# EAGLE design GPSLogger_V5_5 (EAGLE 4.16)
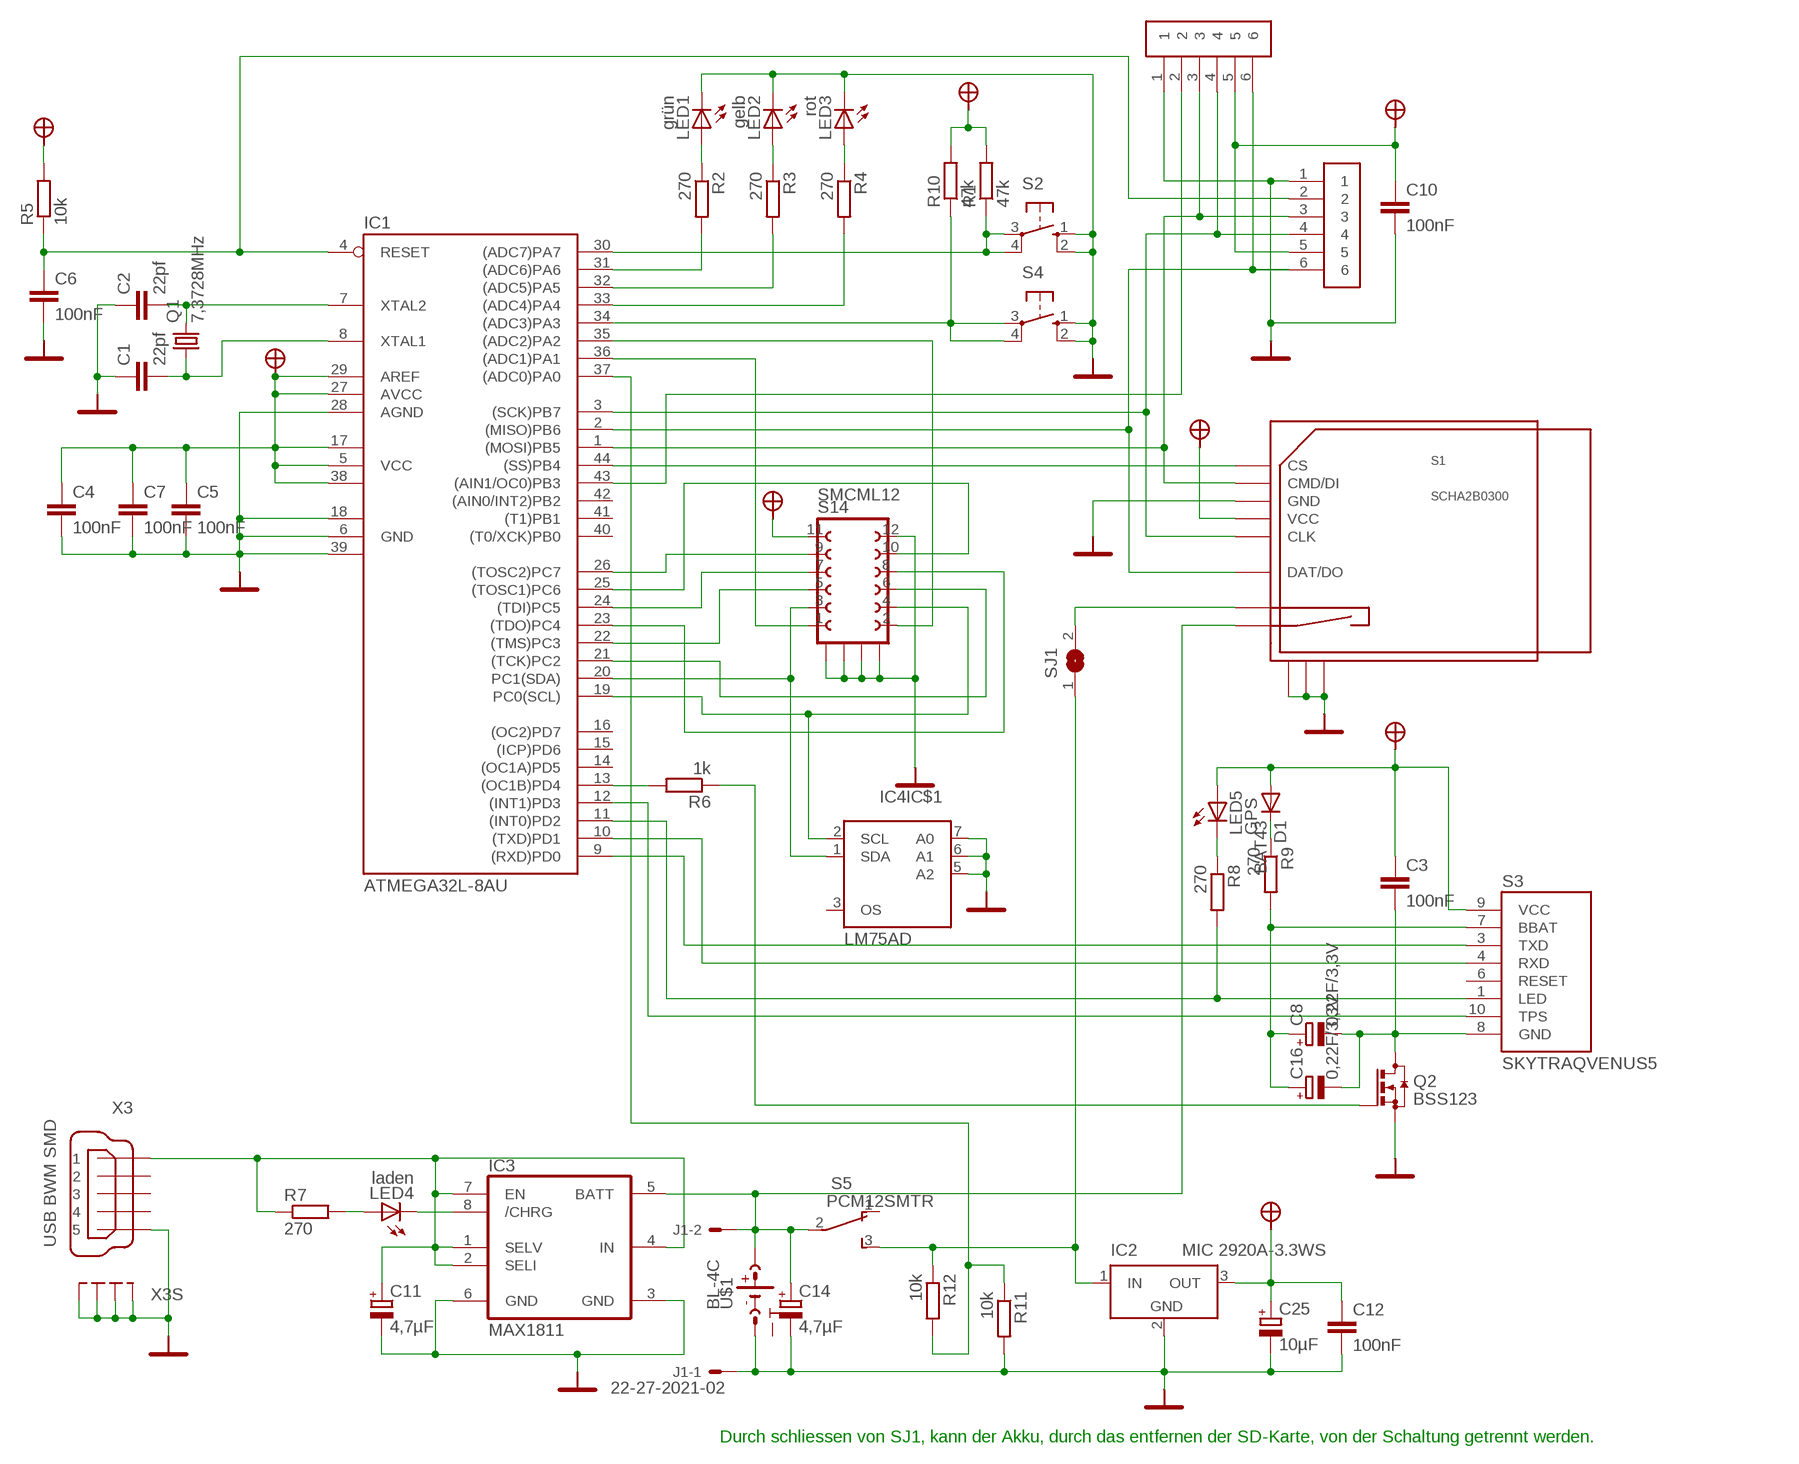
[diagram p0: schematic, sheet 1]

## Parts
C1  22pf  C-EUC0805K  [C0805K]
C2  22pf  C-EUC0805K  [C0805K]
C3  100nF  C-EUC0805K  [C0805K]
C4  100nF  C-EUC0805K  [C0805K]
C5  100nF  C-EUC0805K  [C0805K]
C6  100nF  C-EUC0805K  [C0805K]
C7  100nF  C-EUC0805K  [C0805K]
C8  0,22F/3,3V  EDLEN204XX3R3SA  [EDLEN204A3R3S]
C10  100nF  C-EUC0805K  [C0805K]
C11  4,7µF  CPOL-EUCT3528  [CT3528]
C12  100nF  C-EUC0805K  [C0805K]
C14  4,7µF  CPOL-EUCT3528  [CT3528]
C16  0,22F/3,3V  GOLDCAP  [C]
C25  10µF  CPOL-EUCT3528  [CT3528]
D1  BAT43  DIODE-SOD106A-R  [SOD106A-R]
IC1  ATMEGA32L-8AU  MEGA32-A  [TQFP44]
IC2  MIC 2920A-3.3WS  LT1129CST5  [SOT223]
IC3  MAX1811  [SO08]
IC4  LM75AD  [SO08]
J1  22-27-2021-02  [6410-02]
LED1  grün  LEDCHIPLED_0805  [CHIPLED_0805]
LED2  gelb  LEDCHIPLED_0805  [CHIPLED_0805]
LED3  rot  LEDCHIPLED_0805  [CHIPLED_0805]
LED4  laden  LEDCHIPLED_0805  [CHIPLED_0805]
LED5  GPS  LEDCHIPLED_0805  [CHIPLED_0805]
Q1  7,3728MHz  CRYSTALHC49UP  [HC49UP]
Q2  BSS123  [SOT23]
R1  47k  R-EU_M0805  [M0805]
R2  270  R-EU_M0805  [M0805]
R3  270  R-EU_M0805  [M0805]
R4  270  R-EU_M0805  [M0805]
R5  10k  R-EU_M0805  [M0805]
R6  1k  R-EU_M0805  [M0805]
R7  270  R-EU_M0805  [M0805]
R8  270  R-EU_M0805  [M0805]
R9  270  R-EU_M0805  [M0805]
R10  47k  R-EU_M0805  [M0805]
R11  10k  R-EU_M0805  [M0805]
R12  10k  R-EU_M0805  [M0805]
S1  SCHA2B0300  SD_MICRO  [MICROSD]
S2  10-XX_SMD  [B3F-10XX_SMD]
S3  SKYTRAQVENUS5  [SKYTRAQVENUS5]
S4  10-XX_SMD  [B3F-10XX_SMD]
S5  PCM12SMTR  [PCM12SMTR]
S14  SMCML12  [SMCML12]
SJ1  SJ  [SJ]
U$1  BL-4C  [BL-4C]
U$2  ISP  STECKERSMD6POL  [STECKERSMD6]
U$5  ISP  STECKERSMD6POL  [STECKERSMD6]
X3  USB BWM SMD  MINI-USB_SHIELD5P4-32005-400  [32005-400]

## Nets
3,7V: IC2.1(IN) R12.1 S5.3(S) SJ1.1
5V1: C11.+ IC3.1(SELV) IC3.2(SELI) IC3.4(IN) IC3.7(EN) R7.1 X3.1
BUFFERBATTERIE: C8.+(+1) C16.+(+1) R9.2 S3.7(BBAT)
CS_GPS: IC1.13((OC1B)PD4) R6.2
CS_SD: IC1.44((SS)PB4) S1.2(CS)
GND: C1.1 C2.1 C4.2 C5.2 C6.2 C7.2 C10.2 C11.- C12.2 C14.- C25.- IC1.6(GND) IC1.18(GND1) IC1.28(AGND) IC1.39(GND2) IC2.2(GND) IC3.3(GND) IC3.6(GND) IC4.5(IC$1:A2) IC4.6(IC$1:A1) IC4.7(IC$1:A0) J1.1 LED1.C LED2.C LED3.C Q2.2(S) R11.2 S1.6(GND) S1.GND@1(GND) S1.GND@2(GND) S1.GND@3(GND) S2.1(S) S2.2(S1) S4.1(S) S4.2(S1) S14.12 S14.GND@1 S14.GND@2 S14.GND@3 S14.GND@4 U$1.- U$2.1 U$5.1 X3.5 X3.M1(S1) X3.M2(S2) X3.M3(S3) X3.M4(S4)
GPSTPS: IC1.12((INT1)PD3) S3.10(TPS)
LEDFEHLER: IC1.33((ADC4)PA4) R4.2
LEDGELB: IC1.32((ADC5)PA5) R3.2
LEDGPS: IC1.11((INT0)PD2) R8.2 S3.1(LED)
LEDGRÜN: IC1.31((ADC6)PA6) R2.2
LEDLADEN: IC3.8(/CHRG) LED4.C
MISO: IC1.2((MISO)PB6) S1.7(DAT/DO) U$2.6 U$5.6
MOSI: IC1.1((MOSI)PB5) S1.3(CMD/DI) U$2.3 U$5.3
N$1: IC1.43((AIN1/OC0)PB3) U$5.2
N$2: LED5.C R8.1
N$3: C2.2 IC1.7(XTAL2) Q1.2
N$4: C1.2 IC1.8(XTAL1) Q1.1
N$5: LED1.A R2.1
N$6: LED3.A R4.1
N$12: LED2.A R3.1
N$16: C3.2 C8.-(-1) C16.-(-1) Q2.3(D) S3.8(GND)
N$17: Q2.1(G) R6.1
N$22: S1.S1 SJ1.2
N$23: D1.C R9.1
N$25: LED4.A R7.2
PA0: IC1.37((ADC0)PA0) R11.1 R12.2
PA1: IC1.36((ADC1)PA1) S14.1
PA2: IC1.35((ADC2)PA2) S14.2
PC0: IC1.19(PC0(SCL)) IC4.2(IC$1:SCL) S14.4
PC1: IC1.20(PC1(SDA)) IC4.1(IC$1:SDA) S14.3
PC2: IC1.21((TCK)PC2) S14.6
PC3: IC1.22((TMS)PC3) S14.5
PC4: IC1.23((TDO)PC4) S14.8
PC5: IC1.24((TDI)PC5) S14.7
PC6: IC1.25((TOSC1)PC6) S14.10
PC7: IC1.26((TOSC2)PC7) S14.9
RESET: C6.1 IC1.4(RESET) R5.1 U$2.2
RXD: IC1.9((RXD)PD0) S3.3(TXD)
SCK: IC1.3((SCK)PB7) S1.5(CLK) U$2.4 U$5.4
TASTEROPTIONAL: IC1.34((ADC3)PA3) R10.1 S4.3(P) S4.4(P1)
TASTERSTART: IC1.30((ADC7)PA7) R1.1 S2.3(P) S2.4(P1)
TXD: IC1.10((TXD)PD1) S3.4(RXD)
VBATT: C14.+ IC3.5(BATT) J1.2 S1.S S5.2(P) U$1.+
VCC: C3.1 C4.1 C5.1 C7.1 C10.1 C12.1 C25.+ D1.A IC1.5(VCC) IC1.17(VCC1) IC1.27(AVCC) IC1.29(AREF) IC1.38(VCC2) IC2.3(OUT) LED5.A R1.2 R5.2 R10.2 S1.4(VCC) S3.9(VCC) S14.11 U$2.5 U$5.5
Unconnected: IC1.14((OC1A)PD5) IC1.15((ICP)PD6) IC1.16((OC2)PD7) IC1.40((T0/XCK)PB0) IC1.41((T1)PB1) IC1.42((AIN0/INT2)PB2) IC4.3(IC$1:OS) S3.6(RESET) S5.1(O) U$1.T X3.2 X3.3 X3.4

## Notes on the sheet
- Durch schliessen von SJ1, kann der Akku, durch das entfernen der SD-Karte, von der Schaltung getrennt werden.

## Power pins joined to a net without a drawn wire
GND: IC2.4(GND) IC4.4(PWR:GND) S5.GND@1(GND) S5.GND@2(GND) S5.GND@3(GND) S5.GND@4(GND)
VCC: IC4.8(PWR:VCC)

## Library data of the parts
C1-C7 C10 C12 = rcl:C-EU: CAPACITOR, European symbol
C8 = Sonstige:EDLEN204XX3R3S
C11 C14 C25 = rcl:CPOL-EU: POLARIZED CAPACITOR, European symbol
C16 = Sonstige:GOLDCAP
D1 = diode:DIODE-: DIODE
IC1 = atmel:MEGA32: MICROCONTROLLER 32 Kbytes FLASH 2 Kbytes SRAM 1 Kbytes EEPROM USART 8-channel 10 bit ADC Source: www.atmel.com .. doc2503.pdf
IC2 = linear-technology:LT1129CST5: VOLTAGE REGULATOR with shutdown
IC3 = max1811:MAX1811
IC4 = i2c:LM75AD: Digital Temperature Sensor and Thermal Watchdog
J1 = con-molex:22-?-02: CONNECTOR
LED1-LED5 = led:LED: LED
Q1 = crystal:CRYSTAL: CRYSTAL
Q2 = transistor-small-signal:BSS123: N-CHANNEL MOS FET
R1-R12 = rcl:R-EU_: RESISTOR, European symbol
S1 = MMC:SD_MICRO
S2 S4 = switch-omron:10-XX_SMD
S3 = SkyTraq:SKYTRAQVENUS5
S5 = CKComponents:PCM12SMTR
S14 = Reichelt:SMCML12
SJ1 = jumper:SJ: SMD solder JUMPER
U$1 = Nokia:BL-4C
U$2 U$5 = Sonstige:STECKERSMD6POL
X3 = con-cypressindustries:MINI-USB_SHIELD5P4-: MINI USB-B R/A W/O POST 5 pol. Source: www.cypressindustries.com

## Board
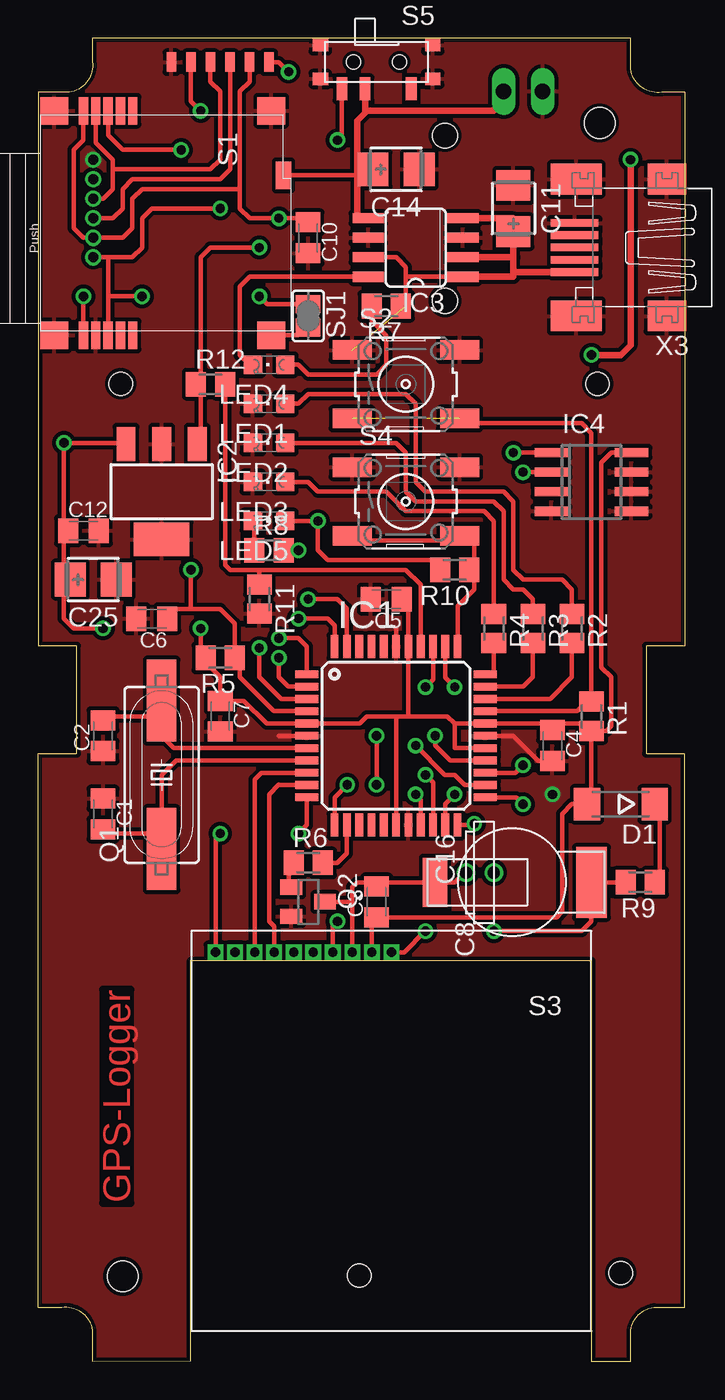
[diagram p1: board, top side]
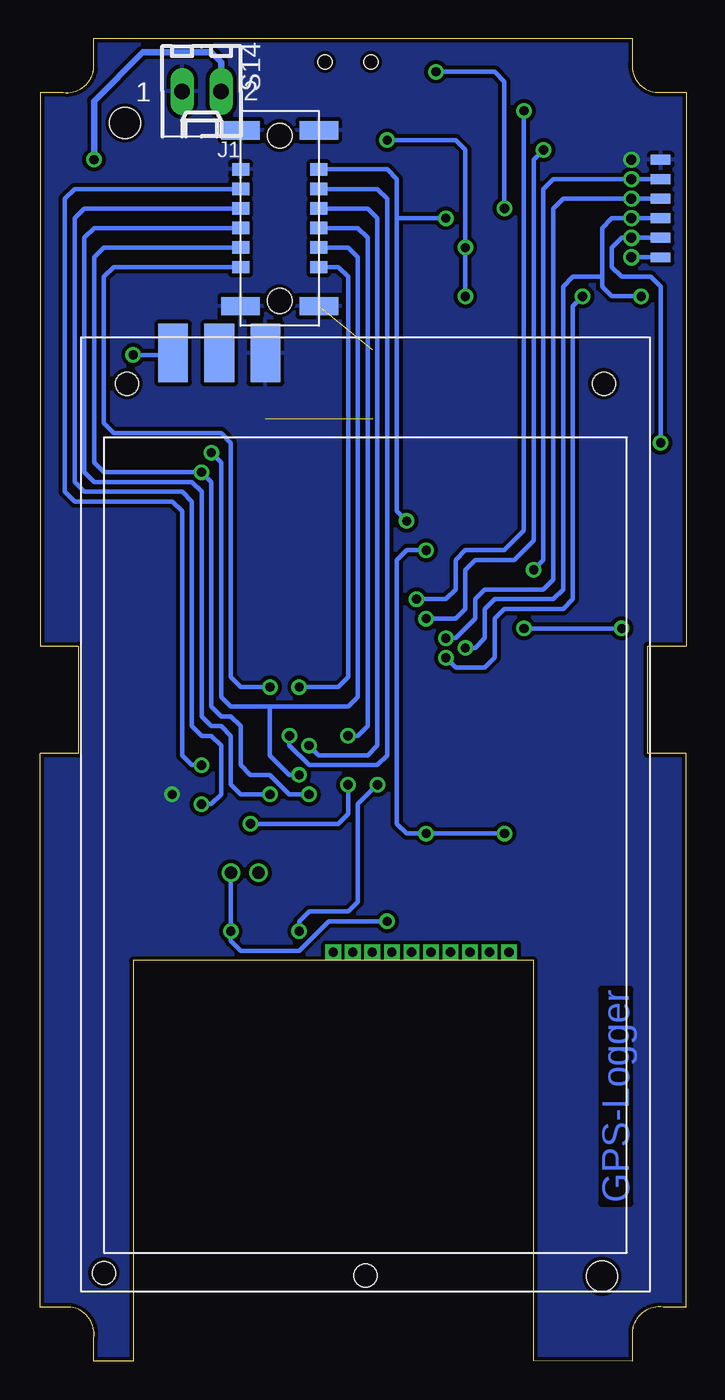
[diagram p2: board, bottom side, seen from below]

Size 42 x 86 mm. Coordinates in mm from the lower left corner, seen from the top.
Outline: 42,3.5 42,39.5 39.5,39.5 39.5,46.5 42,46.5 42,82.5 40.5,82.5 arc-90 38.5,84 38.5,86 3.5,86 3.5,84.5 arc-90 2,82.5 0,82.5 0,46.5 2.5,46.5 2.5,39.5 0,39.5 0,3.5 1.5,3.5 arc-90 3.5,2 3.5,0 9.91,0.01 9.91,26.05 35.95,26.05 35.95,0 38.5,0 38.5,1.5 arc-90 40,3.5 42,3.5
Copper layers (1*16): Top 0.035mm / dielectric 1.5mm / Bottom 0.035mm
Design rules "zwilling": minimum track width 8mil, minimum drill 20mil, track to track 8mil, track to pad 8mil, pad to pad 8mil, via to via 8mil, smd to smd 0mil, copper to edge 10mil, drill to drill 10mil, minimum pad ring 8mil, minimum via ring 8mil, stop-mask expansion 4mil, vias tented up to drill 0mil, thermal gap 10mil
Holes 2 mm at 5.48,5.51 36.48,80.51
Holes 1.5 mm at 37.85,5.73
tKeepout: area 3.5,3.5 to 7.5,7.5; area 34.5,78.5 to 38.5,82.5

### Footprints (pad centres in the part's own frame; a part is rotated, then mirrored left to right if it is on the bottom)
C0805K = smd 1.3 x 1.6: 1 -1,0; 2 1,0
EDLEN204A3R3S = smd 4.6 x 2: + 0,10.16 | smd 3.2 x 1.6: - 0,0
CT3528 = smd 2 x 2.2: + 1.5,0; - -1.5,0
C = drill 0.8 round: + 0,0; - 1.8,0
SOD106A-R = smd 1.7 x 2.1: A 2.2,0; C -2.2,0
TQFP44 = smd 1.5 x 0.5: 1 -5.8,4; 2 -5.8,3.2; 3 -5.8,2.4; 4 -5.8,1.6; 5 -5.8,0.8; 6 -5.8,0; 7 -5.8,-0.8; 8 -5.8,-1.6; 9 -5.8,-2.4; 10 -5.8,-3.2; 11 -5.8,-4; 23 5.8,-4; 24 5.8,-3.2; 25 5.8,-2.4; 26 5.8,-1.6; 27 5.8,-0.8; 28 5.8,0; 29 5.8,0.8; 30 5.8,1.6; 31 5.8,2.4; 32 5.8,3.2; 33 5.8,4 | smd 0.5 x 1.5: 12 -4,-5.8; 13 -3.2,-5.8; 14 -2.4,-5.8; 15 -1.6,-5.8; 16 -0.8,-5.8; 17 0,-5.8; 18 0.8,-5.8; 19 1.6,-5.8; 20 2.4,-5.8; 21 3.2,-5.8; 22 4,-5.8; 34 4,5.8; 35 3.2,5.8; 36 2.4,5.8; 37 1.6,5.8; 38 0.8,5.8; 39 0,5.8; 40 -0.8,5.8; 41 -1.6,5.8; 42 -2.4,5.8; 43 -3.2,5.8; 44 -4,5.8
SOT223 = smd 1.219 x 2.235: 1 -2.311,-3.099; 2 0,-3.099; 3 2.311,-3.099 | smd 3.6 x 2.2: 4 0,3.099
SO08 = smd 0.66 x 2.032: 1 -1.905,-3.073; 2 -0.635,-3.073; 3 0.635,-3.073; 4 1.905,-3.073; 5 1.905,3.073; 6 0.635,3.073; 7 -0.635,3.073; 8 -1.905,3.073
SO08' = smd 0.6 x 2.2: 1 -1.905,-2.6; 2 -0.635,-2.6; 3 0.635,-2.6; 4 1.905,-2.6; 5 1.905,2.6; 6 0.635,2.6; 7 -0.635,2.6; 8 -1.905,2.6
6410-02 = drill 1.016 long: 1 1.27,0; 2 -1.27,0
CHIPLED_0805 = smd 1.2 x 1.2: A 0,-1.05; C 0,1.05
HC49UP = smd 5.334 x 1.93: 1 -4.826,0; 2 4.826,0
SOT23 = smd 1 x 1.4: 1 -0.95,-1.1; 2 0.95,-1.1; 3 0,1.1
M0805 = smd 1.3 x 1.6: 1 -0.95,0; 2 0.95,0
MICROSD = smd 1.8 x 0.6: 1 0,3.2; 2 0,1.6; 3 0,0.8; 4 0,0; 5 14.6,0; 6 14.6,0.8; 7 14.6,1.6; 8 14.6,3.2; NC@1 0,2.4; NC@2 14.6,2.4 | smd 1.8 x 1.8: GND@1 0,-1.9; GND@2 0,12.2; GND@3 14.6,-1.9; S1 14.6,12.2 | smd 1.8 x 1: S 4.2,13
B3F-10XX_SMD = smd 2.54 x 1.27: 1 -3.493,2.223; 2 3.493,2.223; 3 -3.493,-2.223; 4 3.493,-2.223
SKYTRAQVENUS5 = drill 0.6 pad 1.016 square: 1 24.435,1.37; 2 23.165,1.37; 3 21.895,1.37; 4 20.625,1.37; 5 19.355,1.37; 6 18.085,1.37; 7 16.815,1.37; 8 15.545,1.37; 9 14.275,1.37; 10 13.005,1.37
PCM12SMTR = smd 0.7 x 1.5: 1 -2.25,1.75; 2 0.75,1.75; 3 2.25,1.75 | smd 1 x 0.8: GND@1 -3.65,1.1; GND@2 -3.65,-1.1; GND@3 3.65,1.1; GND@4 3.65,-1.1 | hole 0.9: -1.5,0; 1.5,0
SMCML12 = smd 0.8 x 1.1: 1 0,-2.54; 2 0,2.54; 3 1.27,-2.54; 4 1.27,2.54; 5 2.54,-2.54; 6 2.54,2.54; 7 3.81,-2.54; 8 3.81,2.54; 9 5.08,-2.54; 10 5.08,2.54; 11 6.35,-2.54; 12 6.35,2.54 | smd 1.2 x 2.5: GND@1 -2.54,-2.54; GND@2 -2.54,2.54; GND@3 8.89,-2.54; GND@4 8.89,2.54 | hole 1.6: 8.55,0; -2.2,0
SJ = smd 1.168 x 1.6: 1 -0.762,0; 2 0.762,0
BL-4C = smd 1.93 x 3.81: + 6,61; - 12,61; T 9,61 | hole 1.5: 3,59; 34,59; 18.5,1
STECKERSMD6 = smd 0.635 x 1.27: 1 -2.54,0; 2 -1.27,0; 3 0,0; 4 1.27,0; 5 2.54,0; 6 3.81,0
32005-400 = smd 3.1 x 0.5: 1 3,1.6; 2 3,0.8; 3 3,0; 4 3,-0.8; 5 3,-1.6 | smd 2.5 x 2: M1 -3,-4.45; M2 -3,4.45 | smd 3.3 x 2: M3 2.9,4.45; M4 2.9,-4.45

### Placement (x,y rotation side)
C1  4.2,35.57 270 top
C2  4.2,40.65 90 top
C3  21.98,29.86 90 top
C4  33.41,40.02 270 top
C5  22.61,49.54 180 top
C6  7.37,48.27 180 top
C7  11.82,41.92 270 top
C8  25.79,31.13 270 top
C10  17.53,73.04 270 top
C11  30.87,74.94 270 top
C12  2.93,53.99 0 top
C14  23.25,77.48 180 top
C16  29.6,31.76 180 top
C25  3.56,50.81 180 top
D1  37.85,36.21 180 top
IC1  23.25,40.65 0 top
IC2  8.01,56.53 180 top
IC3  24.52,72.4 90 top
IC4  LM75AD  [SO08']  35.95,57.16 270 top
J1  31.5,82.56 180 bottom
LED1  14.99,62.24 90 top
LED2  14.99,59.7 90 top
LED3  14.99,57.16 90 top
LED4  14.99,64.78 90 top
LED5  14.99,54.62 90 top
Q1  8.01,38.11 90 top
Q2  17.53,29.86 270 top
R1  35.95,41.92 270 top
R2  34.68,47.64 270 top
R3  32.14,47.64 270 top
R4  29.6,47.64 270 top
R5  11.82,45.73 180 top
R6  17.53,32.4 0 top
R7  22.61,68.59 180 top
R8  14.99,52.72 0 top
R9  39.12,31.13 180 top
R10  27.06,51.45 180 top
R11  14.36,49.54 270 top
R12  11.18,63.51 0 top
S1  2.93,81.29 270 top
S2  23.88,63.51 0 top
S3  35.95,27.95 180 top
S4  23.88,55.89 0 top
S5  21.98,84.47 180 top
S14  26.42,71.13 90 bottom
SJ1  17.53,67.96 270 top
U$1  39.35,4.55 0 bottom
U$2  1.66,75.58 270 bottom
U$5  11.18,84.47 0 top
X3  37.85,72.4 180 top

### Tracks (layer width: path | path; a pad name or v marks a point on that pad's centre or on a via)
3,7V  (via drill 0.6)
  Top 0.305: S5.3 19.73,79.68 v19.44,79.39 | v14.36,72.4 11.18,72.4 10.55,71.77 10.55,63.51 | IC2.1 10.55,59.63 10.55,63.51 | 10.55,63.51 R12.1 | SJ1.1 14.86,68.72 v14.36,69.23
  Bottom 0.305: v19.44,79.39 14.99,79.39 14.36,78.75 v14.36,72.4 v14.36,69.23
5V1
  Top 0.305: 23.88,70.5 23.88,71.13 23.25,71.77 IC3.7 | 28.33,70.5 IC3.1 23.88,70.5 | R7.1 23.88,68.59 23.88,70.5
  Top 0.406: 28.33,70.5 30.87,70.5 30.87,70.8 | 30.87,71.77 IC3.2 | IC3.4 30.87,74.31 C11.+ 30.87,71.77 | 30.87,70.8 X3.1 | 30.87,70.8 30.87,71.77
BUFFERBATTERIE  (via drill 0.6)
  Top 0.305: R9.2 C8.+ 35.95,28.59 35.31,27.95 v29.6,27.95 | S3.7 19.13,28.28 v19.44,28.59
  Bottom 0.305: v19.44,28.59 23.25,28.59 25.15,26.68 28.96,26.68 29.6,27.32 v29.6,27.95 C16.+
CS_GPS
  Top 0.305: IC1.13 20.05,33.01 19.44,32.4 R6.2
CS_SD  (via drill 0.6)
  Top 0.305: IC1.44 19.25,47.83 18.8,48.27 v16.9,48.27 | v9.28,78.75 5.47,78.75 4.53,79.69 S1.2
  Bottom 0.305: v16.9,48.27 14.99,48.27 14.36,48.91 14.36,51.45 13.72,52.08 11.18,52.08 9.91,53.35 9.91,78.12 v9.28,78.75
GND  (via drill 0.6, 0.65)  (1 unrouted)
  Top 0.305: IC1.6 15.63,40.65 | IC1.39 23.25,47.64 | C4.2 32.5,39.02 30.87,40.65 IC1.28
  other vias: 33.41,36.84 3.56,78.12
  pour Top (isolate 0.254): -0.88,87.64 43.57,87.64 43.57,0.01 -0.88,0.01
  pour Bottom (isolate 0.254): -0.88,87.64 43.57,87.64 43.57,0.01 -0.88,0.01
GPSTPS  (via drill 0.6)
  Top 0.305: S3.10 23.78,26.58 v25.15,27.95 | IC1.12 19.25,36.65 v20.07,37.48
  Bottom 0.305: v25.15,27.95 25.15,28.59 24.52,29.22 21.98,29.22 21.34,29.86 21.34,36.21 v20.07,37.48
LEDFEHLER
  Top 0.305: IC1.33 29.6,44.65 R4.2
LEDGELB
  Top 0.305: IC1.32 31.53,43.85 32.14,44.46 R3.2
LEDGPS  (via drill 0.6)
  Top 0.305: IC1.11 17.45,34.85 v16.9,34.3 | S3.1 11.51,34 v11.82,34.3 | v16.9,52.72 R8.2
  Bottom 0.305: v11.82,34.3 v16.9,34.3 18.17,34.3 18.8,34.94 18.8,52.08 18.17,52.72 v16.9,52.72
LEDGRÜN
  Top 0.305: IC1.31 33.27,43.05 34.68,44.46 R2.2
LEDLADEN
  Top 0.305: IC3.8 13.72,70.5 13.09,69.86 13.09,65.42 13.72,64.78 LED4.C
MISO  (via drill 0.6, 0.65)
  Top 0.305: IC1.2 16.24,43.85 15.63,44.46 v15.63,45.73 | 4.53,69.23 S1.7 | v6.74,69.23 4.53,69.23 | 4.53,71.77 6.1,71.77 6.74,72.4 6.74,74.31 7.37,74.94 v11.82,74.94 | 4.53,69.23 4.53,71.77 | 4.53,71.77 v3.56,71.77 | v16.26,83.83 15.63,84.47 U$5.6
  Bottom 0.305: v15.63,45.73 14.99,45.1 13.09,45.1 12.45,45.73 12.45,48.27 11.82,48.91 8.01,48.91 7.37,49.54 7.37,68.59 v6.74,69.23 | v3.56,71.77 U$2.6 | v11.82,74.94 11.82,83.2 12.45,83.83 v16.26,83.83
MOSI  (via drill 0.6, 0.65)
  Top 0.305: IC1.1 17.45,46.45 16.9,47 v15.63,47 | v3.56,75.58 4.2,75.58 4.83,76.21 4.83,77.48 | 4.83,77.48 4.83,78.12 3.73,79.22 S1.3 | U$5.3 11.18,83.2 11.82,82.56 11.82,78.12 11.18,77.48 4.83,77.48
  Bottom 0.305: U$2.3 v3.56,75.58 8.01,75.58 8.64,74.94 8.64,50.81 9.28,50.18 13.09,50.18 13.72,49.54 13.72,48.27 14.99,47 v15.63,47
N$1  (via drill 0.6)
  Top 0.305: IC1.43 20.05,48.93 19.44,49.54 v17.53,49.54 | v10.55,81.29 9.91,81.93 U$5.2
  Bottom 0.305: v17.53,49.54 15.63,49.54 14.99,50.18 14.99,52.08 14.36,52.72 11.82,52.72 10.55,53.99 v10.55,81.29
N$2
  Top 0.305: LED5.C 13.72,54.62 14.04,54.31 R8.1
N$3
  Top 0.305: C2.2 4.2,41.92 8.01,41.92 Q1.2 8.01,40.65 8.81,39.85 IC1.7
N$4
  Top 0.305: IC1.8 8.95,39.05 8.01,38.11 Q1.1 8.01,34.3 4.2,34.3 C1.2
N$5
  Top 0.305: LED1.A 16.9,62.24 17.53,62.88 23.88,62.88 24.52,62.24 24.52,57.16 25.15,56.53 30.23,56.53 30.87,55.89 30.87,51.45 31.5,50.81 34.04,50.81 34.68,50.18 R2.1
N$6
  Top 0.305: LED3.A 17.53,57.16 18.17,56.53 22.61,56.53 23.88,55.26 28.96,55.26 29.6,54.62 R4.1
N$12
  Top 0.305: LED2.A 23.25,59.7 23.88,59.07 23.88,56.53 24.52,55.89 29.6,55.89 30.23,55.26 30.23,50.81 30.87,50.18 31.5,50.18 32.14,49.54 R3.1
N$16
  Top 0.305: C16.- 27.69,31.76 27.06,31.13 C8.- 21.98,31.13 | 21.98,31.13 20.71,31.13 20.4,30.82 | S3.8 20.4,30.82 | 21.98,31.13 C3.2 | 20.4,30.82 20.4,29.86 Q2.3
N$17
  Top 0.305: R6.1 16.26,32.4 16.26,30.81 Q2.1
N$22
  Top 0.305: SJ1.2 17.53,67.32 16.9,66.69 S1.S1
N$23
  Top 0.305: D1.C 40.39,36.21 40.39,31.13 R9.1
N$25
  Top 0.305: LED4.A 16.9,64.78 17.53,64.15 21.98,64.15 22.61,64.78 22.61,66.69 21.66,67.64 R7.2
PA0
  Top 0.305: IC1.37 24.85,50.48 23.88,51.45 14.36,51.45 | R12.2 12.13,51.77 12.45,51.45 14.36,51.45 | R11.1 14.36,51.45
PA1  (via drill 0.6)
  Top 0.305: IC1.36 25.65,44.32 v25.15,43.83
  Bottom 0.305: v25.15,43.83 22.61,43.83 21.98,44.46 21.98,70.5 22.61,71.13 S14.1
PA2  (via drill 0.6)
  Top 0.305: IC1.35 26.45,44.44 v27.06,43.83
  Bottom 0.305: v27.06,43.83 28.96,43.83 29.6,44.46 29.6,59.7 30.23,60.34 37.22,60.34 37.85,60.97 37.85,70.5 37.22,71.13 S14.2
PC0  (via drill 0.6)
  Top 0.305: IC1.19 24.85,36.51 v24.52,36.84 | v31.5,57.8 IC4.2
  Bottom 0.305: S14.4 37.85,72.4 38.49,71.77 38.49,59.7 38.49,58.43 37.85,57.8 v31.5,57.8 30.87,57.16 30.87,42.56 30.23,41.92 29.6,41.92 28.96,41.29 28.96,38.75 28.33,38.11 27.06,38.11 25.79,36.84 v24.52,36.84
PC1  (via drill 0.6)
  Top 0.305: IC1.20 25.65,37.62 v25.15,38.11 | v30.87,59.07 IC4.1
  Bottom 0.305: S14.3 21.98,72.4 21.34,71.77 21.34,43.19 21.98,42.56 27.06,42.56 | 27.06,42.56 27.06,39.38 25.79,38.11 v25.15,38.11 | v30.87,59.07 30.23,58.43 30.23,43.19 29.6,42.56 27.06,42.56
PC2  (via drill 0.6)
  Top 0.305: IC1.21 26.45,36.23 v27.06,36.84
  Bottom 0.305: S14.6 38.49,73.67 39.12,73.04 39.12,57.8 38.49,57.16 32.14,57.16 31.5,56.53 31.5,41.92 30.87,41.29 30.23,41.29 29.6,40.65 29.6,37.48 28.96,36.84 v27.06,36.84
PC3  (via drill 0.6)
  Top 0.305: IC1.22 28.24,34.85 v28.33,34.94 | v21.98,37.48 v21.98,40.65
  Bottom 0.305: S14.5 21.34,73.67 20.71,73.04 20.71,41.29 21.34,40.65 v21.98,40.65 | v21.98,37.48 21.98,35.57 22.61,34.94 v28.33,34.94
PC4  (via drill 0.6)
  Top 0.305: IC1.23 31.06,36.65 v31.5,36.21
  Bottom 0.305: S14.8 39.12,74.94 39.76,74.31 39.76,57.16 39.12,56.53 32.77,56.53 32.14,55.89 32.14,41.29 31.5,40.65 30.87,40.65 30.23,40.02 30.23,36.84 30.87,36.21 v31.5,36.21
PC5  (via drill 0.6)
  Top 0.305: IC1.24 27.72,37.45 27.06,38.11 26.42,38.11 v24.52,40.02
  Bottom 0.305: S14.7 20.71,74.94 20.07,74.31 20.07,40.02 20.71,39.38 23.88,39.38 v24.52,40.02
PC6  (via drill 0.6)
  Top 0.305: IC1.25 31.01,38.25 v31.5,38.75
  Bottom 0.305: S14.10 39.76,76.21 40.39,75.58 40.39,56.53 39.76,55.89 33.41,55.89 32.77,55.26 32.77,39.38 32.14,38.75 v31.5,38.75
PC7  (via drill 0.6)
  Top 0.305: IC1.26 26.75,39.05 25.79,40.02 v25.79,40.65
  Bottom 0.305: S14.9 20.07,76.21 19.44,75.58 19.44,39.38 20.07,38.75 24.52,38.75 25.79,40.02 v25.79,40.65
RESET  (via drill 0.6, 0.65)
  Top 0.305: IC1.4 15.3,42.25 13.09,44.46 13.09,45.73 R5.1 12.77,47.96 11.82,48.91 9.91,48.91 | C6.1 8.64,48.91 9.91,48.91 | 9.91,48.91 v9.91,51.45
  Bottom 0.305: v9.91,51.45 9.28,52.08 9.28,76.21 8.64,76.85 v3.56,76.85 U$2.2
RXD
  Top 0.305: IC1.9 14.5,38.25 14.05,37.81 S3.3
SCK  (via drill 0.6, 0.65)
  Top 0.305: IC1.3 15.77,43.05 14.36,44.46 v14.36,46.37 | v2.93,69.23 S1.5 | U$5.4 12.45,77.48 11.82,76.85 6.1,76.85 5.47,76.21 5.47,74.94 4.83,74.31 v3.56,74.31
  Bottom 0.305: v14.36,46.37 13.72,46.37 13.09,47 13.09,48.91 12.45,49.54 8.64,49.54 8.01,50.18 8.01,69.86 7.37,70.5 5.47,70.5 | U$2.4 v3.56,74.31 4.83,74.31 5.47,73.67 5.47,70.5 | 5.47,70.5 5.47,69.86 4.83,69.23 v2.93,69.23
TASTEROPTIONAL
  Top 0.305: S4.3 20.39,53.35 27.25,53.35 | S4.4 27.37,53.35 27.25,53.35 | IC1.34 27.25,49.1 28.33,50.18 28.33,51.45 | 27.25,53.35 28.33,53.35 28.33,51.45 | 28.33,51.45 R10.1
TASTERSTART  (1 unrouted)
  Top 0.305: IC1.30 35.01,42.25 35.95,43.19 R1.1 35.95,60.34 35.31,60.97 27.69,60.97 S2.4
TXD
  Top 0.305: 15.63,37.45 15.6,37.45 | 15.63,37.45 IC1.10 | S3.4 15.32,28.26 14.99,28.59 14.99,36.84 15.63,37.48 15.63,37.45
VBATT  (via drill 0.6)
  Top 0.305: S5.2 21.23,82.56 | 20.71,74.31 IC3.5 | S1.S 20.71,77.09
  Top 0.406: 20.71,77.48 20.71,77.09 20.71,74.31 | 20.71,77.48 C14.+ | 21.23,81.29 21.23,81.18 20.71,80.66 20.71,77.48 | 21.23,81.29 S5.2 | 21.23,81.29 29.6,81.29 30.23,81.93 J1.2 | v35.95,65.42 37.85,65.42 38.49,66.05 v38.49,78.12
  Bottom 0.305: U$1.+ 33.35,65.42 v35.95,65.42
  Bottom 0.406: v38.49,78.12 38.49,81.93 35.31,85.1 30.87,85.1 30.23,84.47 J1.2
VCC  (via drill 0.6, 0.65)
  Top 0.305: IC1.27 27.06,39.85 27.06,41.45 | 27.06,41.45 IC1.29 35.15,41.45 | C5.1 23.88,49.54 24.05,49.38 IC1.38 24.05,41.92 | v10.55,47.64 10.55,45.73 R5.2 10.87,45.41 11.82,44.46 C7.1 13.36,42.92 14.83,41.45 IC1.5 20.87,41.45 21.34,41.92 23.25,41.92 | 35.95,40.65 R1.2 36.9,40.97 37.22,41.29 37.22,44.46 36.58,45.1 36.58,58.43 37.22,59.07 IC4.8 | 35.95,40.65 35.15,41.45 | 23.25,38.11 IC1.17 23.25,41.92 | 35.15,41.45 33.41,41.45 C4.1 | 27.06,41.45 26.59,41.92 24.05,41.92 | 24.05,41.92 23.25,41.92 | S3.9 21.67,28.28 21.98,28.59 C3.1 33.68,28.86 34.04,29.22 34.04,35.57 34.68,36.21 D1.A 35.95,36.5 35.95,40.65 | R10.2 26.11,52.08 18.8,52.08 18.17,52.72 v18.17,54.62 LED5.A | S1.4 2.93,79.39 2.29,78.75 2.29,73.67 2.93,73.04 v3.56,73.04 5.47,73.04 6.1,73.67 6.1,75.58 6.74,76.21 13.09,76.21 | IC2.3 5.7,59.7 v1.66,59.7 1.66,53.99 | v4.2,47.64 2.29,47.64 1.66,48.27 1.66,50.81 | 1.66,50.81 1.66,53.99 | 1.66,50.81 C25.+ | 1.66,53.99 C12.1 | C10.1 17.53,74.31 v15.63,74.31 13.72,74.31 13.09,74.94 13.09,76.21 | 13.09,76.21 13.09,82.56 13.72,83.2 U$5.5
  Bottom 0.305: v10.55,47.64 v4.2,47.64 | v15.63,74.31 18.8,74.31 | S14.11 19.44,77.48 18.8,76.85 18.8,74.31 | v18.17,54.62 18.8,55.26 18.8,74.31 | U$2.5 v3.56,73.04 4.2,73.04 4.83,72.4 4.83,71.13 4.2,70.5 2.29,70.5 1.66,69.86 v1.66,59.7

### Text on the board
Top: GPS-Logger
Bottom: GPS-Logger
